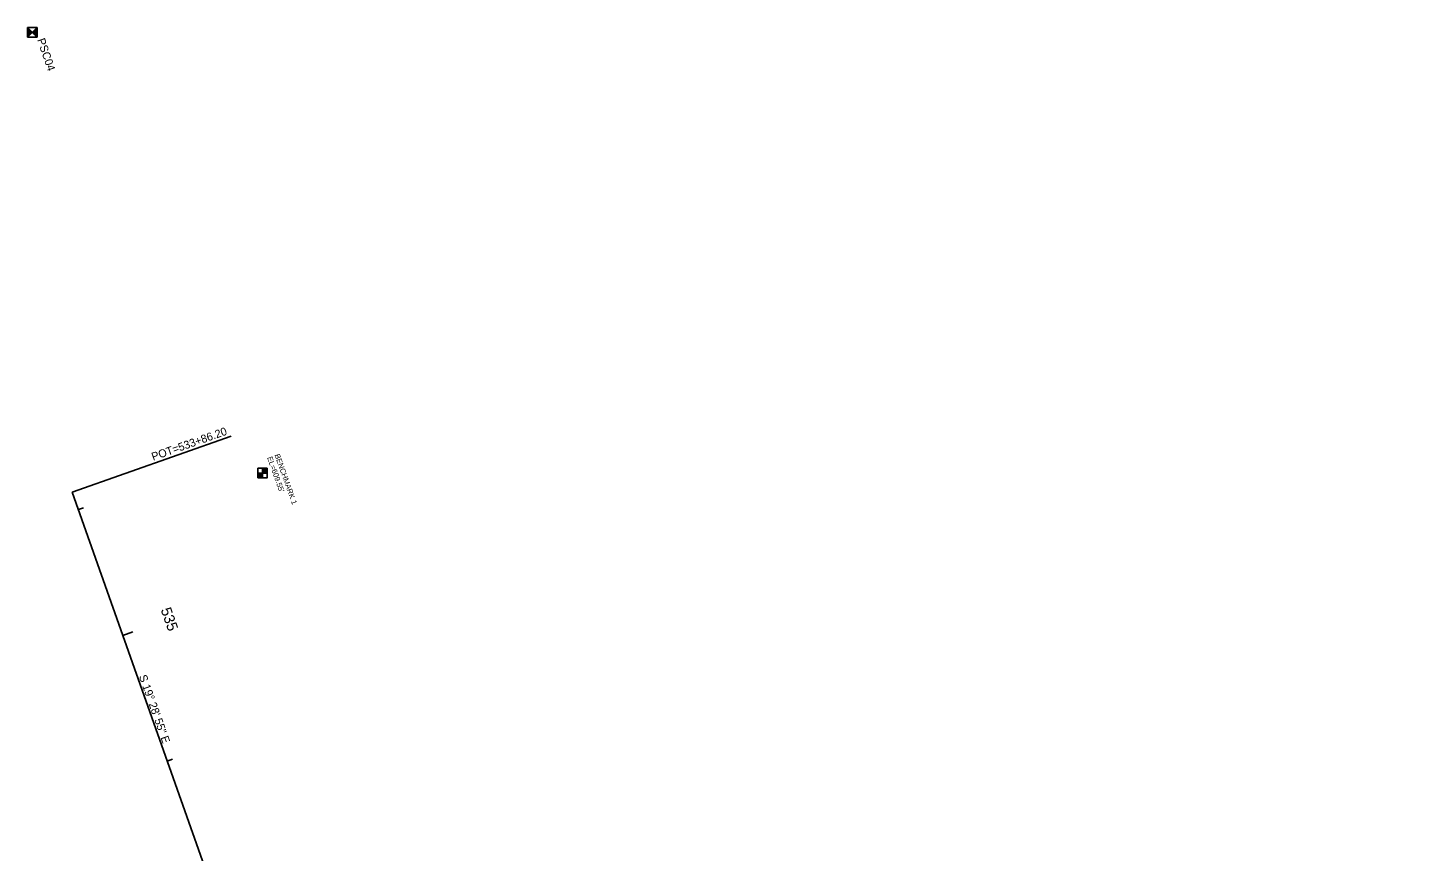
# Model space of a CAD drawing. Extents: x 2004390 to 2008791, y 1133870 to 1140084.
# Drawn here: x 2005003 to 2006039, y 1139364 to 1139982 of the extents above; entities that cross this region are included whole.
import ezdxf

# ---------------------------------------------------------------- set-up
doc = ezdxf.new("R2010")
doc.units = 0
for name, color, linetype in [('RD_HC_Cl', 7, 'Continuous'), ('RD_HC_Data', 7, 'Continuous'), ('RD_HC_Data_Tic', 7, 'Continuous'), ('RD_HC_Survey', 7, 'Continuous'), ('RD_HC_Survey_txCode', 7, 'Continuous'), ('RD_HC_TX_Sta50', 7, 'Continuous')]:
    doc.layers.add(name, color=color, linetype=linetype)

msp = doc.modelspace()

# ---------------------------------------------------------------- linework, layer by layer
at = {"layer": 'RD_HC_Cl'}
msp.add_line((2005036.1, 1139633.5), (2007075.2, 1133869.8), dxfattribs=at)
at = {"layer": 'RD_HC_Data'}
msp.add_line((2005036.1, 1139633.5), (2005155.4, 1139675.7), dxfattribs=at)
at = {"layer": 'RD_HC_Data_Tic'}
for p, q in [((2005040.7, 1139620.5), (2005044.5, 1139621.9)), ((2005074.1, 1139526.2), (2005081.6, 1139528.9)), ((2005107.4, 1139432), (2005111.2, 1139433.3))]:
    msp.add_line(p, q, dxfattribs=at)
at = {"layer": 'RD_HC_Survey'}
for p, q in [((2005002.6, 1139981.9), (2005009.7, 1139974.8)), ((2005009.7, 1139981.9), (2005002.6, 1139974.8)), ((2005002.7, 1139981.8), (2005002.7, 1139974.9)), ((2005002.7, 1139981.8), (2005002.7, 1139974.9)), ((2005002.8, 1139981.7), (2005002.8, 1139975)), ((2005002.8, 1139981.7), (2005002.8, 1139975)), ((2005002.9, 1139981.6), (2005002.9, 1139975.1)), ((2005002.9, 1139981.6), (2005002.9, 1139975.1)), ((2005003, 1139981.5), (2005003, 1139975.2)), ((2005003, 1139981.5), (2005003, 1139975.2)), ((2005003.1, 1139981.4), (2005003.1, 1139975.3)), ((2005003.1, 1139981.4), (2005003.1, 1139975.3)), ((2005003.2, 1139981.3), (2005003.2, 1139975.4)), ((2005003.2, 1139981.3), (2005003.2, 1139975.4)), ((2005003.3, 1139981.2), (2005003.3, 1139975.5)), ((2005003.3, 1139981.2), (2005003.3, 1139975.5)), ((2005003.4, 1139981.1), (2005003.4, 1139975.6)), ((2005003.4, 1139981.1), (2005003.4, 1139975.6)), ((2005003.5, 1139981), (2005003.5, 1139975.7)), ((2005003.5, 1139981), (2005003.5, 1139975.7)), ((2005003.6, 1139980.9), (2005003.6, 1139975.8)), ((2005003.6, 1139980.9), (2005003.6, 1139975.8)), ((2005003.7, 1139980.8), (2005003.7, 1139975.9)), ((2005003.7, 1139980.8), (2005003.7, 1139975.9)), ((2005003.8, 1139980.7), (2005003.8, 1139976)), ((2005003.8, 1139980.7), (2005003.8, 1139976)), ((2005003.9, 1139980.6), (2005003.9, 1139976.1)), ((2005003.9, 1139980.6), (2005003.9, 1139976.1)), ((2005004, 1139980.5), (2005004, 1139976.2)), ((2005004, 1139980.5), (2005004, 1139976.2)), ((2005004.1, 1139980.4), (2005004.1, 1139976.3)), ((2005004.1, 1139980.4), (2005004.1, 1139976.3)), ((2005004.2, 1139980.3), (2005004.2, 1139976.4)), ((2005004.2, 1139980.3), (2005004.2, 1139976.4)), ((2005004.3, 1139980.2), (2005004.3, 1139976.5)), ((2005004.3, 1139980.2), (2005004.3, 1139976.5)), ((2005004.4, 1139980.1), (2005004.4, 1139976.6)), ((2005004.4, 1139980.1), (2005004.4, 1139976.6)), ((2005004.5, 1139980), (2005004.5, 1139976.7)), ((2005004.5, 1139980), (2005004.5, 1139976.7)), ((2005004.6, 1139979.9), (2005004.6, 1139976.8)), ((2005004.6, 1139979.9), (2005004.6, 1139976.8)), ((2005004.7, 1139979.8), (2005004.7, 1139976.9)), ((2005004.7, 1139979.8), (2005004.7, 1139976.9)), ((2005004.8, 1139979.7), (2005004.8, 1139977)), ((2005004.8, 1139979.7), (2005004.8, 1139977)), ((2005004.9, 1139979.6), (2005004.9, 1139977.1)), ((2005004.9, 1139979.6), (2005004.9, 1139977.1)), ((2005005, 1139979.5), (2005005, 1139977.2)), ((2005005, 1139979.5), (2005005, 1139977.2)), ((2005005.1, 1139979.4), (2005005.1, 1139977.3)), ((2005005.1, 1139979.4), (2005005.1, 1139977.3)), ((2005005.2, 1139979.3), (2005005.2, 1139977.4)), ((2005005.2, 1139979.3), (2005005.2, 1139977.4)), ((2005005.3, 1139979.2), (2005005.3, 1139977.5)), ((2005005.3, 1139979.2), (2005005.3, 1139977.5)), ((2005005.4, 1139979.1), (2005005.4, 1139977.6)), ((2005005.4, 1139979.1), (2005005.4, 1139977.6)), ((2005005.5, 1139979), (2005005.5, 1139977.7)), ((2005005.5, 1139979), (2005005.5, 1139977.7)), ((2005005.6, 1139978.9), (2005005.6, 1139977.8)), ((2005005.6, 1139978.9), (2005005.6, 1139977.8)), ((2005005.7, 1139978.8), (2005005.7, 1139977.9)), ((2005005.7, 1139978.8), (2005005.7, 1139977.9)), ((2005005.8, 1139978.7), (2005005.8, 1139978)), ((2005005.8, 1139978.7), (2005005.8, 1139978)), ((2005005.9, 1139978.6), (2005005.9, 1139978.1)), ((2005005.9, 1139978.6), (2005005.9, 1139978.1)), ((2005006, 1139978.5), (2005006, 1139978.2)), ((2005006, 1139978.5), (2005006, 1139978.2)), ((2005006.1, 1139978.4), (2005006.1, 1139978.3)), ((2005006.1, 1139978.4), (2005006.1, 1139978.3)), ((2005006.2, 1139978.4), (2005006.2, 1139978.3)), ((2005006.3, 1139978.5), (2005006.3, 1139978.2)), ((2005006.3, 1139978.4), (2005006.3, 1139978.3)), ((2005006.4, 1139978.6), (2005006.4, 1139978.1)), ((2005006.4, 1139978.5), (2005006.4, 1139978.2)), ((2005006.5, 1139978.7), (2005006.5, 1139978)), ((2005006.5, 1139978.6), (2005006.5, 1139978.1)), ((2005006.6, 1139978.8), (2005006.6, 1139977.9)), ((2005006.6, 1139978.7), (2005006.6, 1139978)), ((2005006.7, 1139978.9), (2005006.7, 1139977.8)), ((2005006.7, 1139978.8), (2005006.7, 1139977.9)), ((2005006.8, 1139979), (2005006.8, 1139977.7)), ((2005006.8, 1139978.9), (2005006.8, 1139977.8)), ((2005006.9, 1139979.1), (2005006.9, 1139977.6)), ((2005006.9, 1139979), (2005006.9, 1139977.7)), ((2005007, 1139979.2), (2005007, 1139977.5)), ((2005007, 1139979.1), (2005007, 1139977.6)), ((2005007.1, 1139979.3), (2005007.1, 1139977.4)), ((2005007.1, 1139979.2), (2005007.1, 1139977.5)), ((2005007.2, 1139979.4), (2005007.2, 1139977.3)), ((2005007.2, 1139979.3), (2005007.2, 1139977.4)), ((2005007.3, 1139979.5), (2005007.3, 1139977.2)), ((2005007.3, 1139979.4), (2005007.3, 1139977.3)), ((2005007.4, 1139979.6), (2005007.4, 1139977.1)), ((2005007.4, 1139979.5), (2005007.4, 1139977.2)), ((2005007.5, 1139979.7), (2005007.5, 1139977)), ((2005007.5, 1139979.6), (2005007.5, 1139977.1)), ((2005007.6, 1139979.8), (2005007.6, 1139976.9)), ((2005007.6, 1139979.7), (2005007.6, 1139977)), ((2005007.7, 1139979.9), (2005007.7, 1139976.8)), ((2005007.7, 1139979.8), (2005007.7, 1139976.9)), ((2005007.8, 1139980), (2005007.8, 1139976.7)), ((2005007.8, 1139979.9), (2005007.8, 1139976.8)), ((2005007.9, 1139980.1), (2005007.9, 1139976.6)), ((2005007.9, 1139980), (2005007.9, 1139976.7)), ((2005008, 1139980.2), (2005008, 1139976.5)), ((2005008, 1139980.1), (2005008, 1139976.6)), ((2005008.1, 1139980.3), (2005008.1, 1139976.4)), ((2005008.1, 1139980.2), (2005008.1, 1139976.5)), ((2005008.2, 1139980.4), (2005008.2, 1139976.3)), ((2005008.2, 1139980.3), (2005008.2, 1139976.4)), ((2005008.3, 1139980.5), (2005008.3, 1139976.2)), ((2005008.3, 1139980.4), (2005008.3, 1139976.3)), ((2005008.4, 1139980.6), (2005008.4, 1139976.1)), ((2005008.4, 1139980.5), (2005008.4, 1139976.2)), ((2005008.5, 1139980.7), (2005008.5, 1139976)), ((2005008.5, 1139980.6), (2005008.5, 1139976.1)), ((2005008.6, 1139980.8), (2005008.6, 1139975.9)), ((2005008.6, 1139980.7), (2005008.6, 1139976)), ((2005008.7, 1139980.9), (2005008.7, 1139975.8)), ((2005008.7, 1139980.8), (2005008.7, 1139975.9)), ((2005008.8, 1139981), (2005008.8, 1139975.7)), ((2005008.8, 1139980.9), (2005008.8, 1139975.8)), ((2005008.9, 1139981.1), (2005008.9, 1139975.6)), ((2005008.9, 1139981), (2005008.9, 1139975.7)), ((2005009, 1139981.2), (2005009, 1139975.5)), ((2005009, 1139981.1), (2005009, 1139975.6)), ((2005009.1, 1139981.3), (2005009.1, 1139975.4)), ((2005009.1, 1139981.2), (2005009.1, 1139975.5)), ((2005009.2, 1139981.4), (2005009.2, 1139975.3)), ((2005009.2, 1139981.3), (2005009.2, 1139975.4)), ((2005009.3, 1139981.5), (2005009.3, 1139975.2)), ((2005009.3, 1139981.4), (2005009.3, 1139975.3)), ((2005009.4, 1139981.6), (2005009.4, 1139975.1)), ((2005009.4, 1139981.5), (2005009.4, 1139975.2)), ((2005009.5, 1139981.7), (2005009.5, 1139975)), ((2005009.5, 1139981.6), (2005009.5, 1139975.1)), ((2005009.6, 1139981.8), (2005009.6, 1139974.9)), ((2005009.6, 1139981.7), (2005009.6, 1139975)), ((2005009.7, 1139981.8), (2005009.7, 1139974.9)), ((2005178.8, 1139651.5), (2005178.8, 1139644.4)), ((2005178.9, 1139651.5), (2005178.9, 1139647.9)), ((2005178.9, 1139651.5), (2005178.9, 1139647.9)), ((2005179, 1139651.5), (2005179, 1139647.9)), ((2005179, 1139651.5), (2005179, 1139647.9)), ((2005179.1, 1139651.5), (2005179.1, 1139647.9)), ((2005179.1, 1139651.5), (2005179.1, 1139647.9)), ((2005179.2, 1139651.5), (2005179.2, 1139647.9)), ((2005179.2, 1139651.5), (2005179.2, 1139647.9)), ((2005179.3, 1139651.5), (2005179.3, 1139647.9)), ((2005179.3, 1139651.5), (2005179.3, 1139647.9)), ((2005179.4, 1139651.5), (2005179.4, 1139647.9)), ((2005179.4, 1139651.5), (2005179.4, 1139647.9)), ((2005179.5, 1139651.5), (2005179.5, 1139647.9)), ((2005179.5, 1139651.5), (2005179.5, 1139647.9)), ((2005179.6, 1139651.5), (2005179.6, 1139647.9)), ((2005179.6, 1139651.5), (2005179.6, 1139647.9)), ((2005179.7, 1139651.5), (2005179.7, 1139647.9)), ((2005179.7, 1139651.5), (2005179.7, 1139647.9)), ((2005179.8, 1139651.5), (2005179.8, 1139647.9)), ((2005179.8, 1139651.5), (2005179.8, 1139647.9)), ((2005179.9, 1139651.5), (2005179.9, 1139647.9)), ((2005179.9, 1139651.5), (2005179.9, 1139647.9)), ((2005180, 1139651.5), (2005180, 1139647.9)), ((2005180, 1139651.5), (2005180, 1139647.9)), ((2005180.1, 1139651.5), (2005180.1, 1139647.9)), ((2005180.1, 1139651.5), (2005180.1, 1139647.9)), ((2005180.2, 1139651.5), (2005180.2, 1139647.9)), ((2005180.2, 1139651.5), (2005180.2, 1139647.9)), ((2005180.3, 1139651.5), (2005180.3, 1139647.9)), ((2005180.3, 1139651.5), (2005180.3, 1139647.9)), ((2005180.4, 1139651.5), (2005180.4, 1139647.9)), ((2005180.4, 1139651.5), (2005180.4, 1139647.9)), ((2005180.5, 1139651.5), (2005180.5, 1139647.9)), ((2005180.5, 1139651.5), (2005180.5, 1139647.9)), ((2005180.6, 1139651.5), (2005180.6, 1139647.9)), ((2005180.6, 1139651.5), (2005180.6, 1139647.9)), ((2005180.7, 1139651.5), (2005180.7, 1139647.9)), ((2005180.7, 1139651.5), (2005180.7, 1139647.9)), ((2005180.8, 1139651.5), (2005180.8, 1139647.9)), ((2005180.8, 1139651.5), (2005180.8, 1139647.9)), ((2005180.9, 1139651.5), (2005180.9, 1139647.9)), ((2005180.9, 1139651.5), (2005180.9, 1139647.9)), ((2005181, 1139651.5), (2005181, 1139647.9)), ((2005181, 1139651.5), (2005181, 1139647.9)), ((2005181.1, 1139651.5), (2005181.1, 1139647.9)), ((2005181.1, 1139651.5), (2005181.1, 1139647.9)), ((2005181.2, 1139651.5), (2005181.2, 1139647.9)), ((2005181.2, 1139651.5), (2005181.2, 1139647.9)), ((2005181.3, 1139651.5), (2005181.3, 1139647.9)), ((2005181.3, 1139651.5), (2005181.3, 1139647.9)), ((2005181.4, 1139651.5), (2005181.4, 1139647.9)), ((2005181.4, 1139651.5), (2005181.4, 1139647.9)), ((2005181.5, 1139651.5), (2005181.5, 1139647.9)), ((2005181.5, 1139651.5), (2005181.5, 1139647.9)), ((2005181.6, 1139651.5), (2005181.6, 1139647.9)), ((2005181.6, 1139651.5), (2005181.6, 1139647.9)), ((2005181.7, 1139651.5), (2005181.7, 1139647.9)), ((2005181.7, 1139651.5), (2005181.7, 1139647.9)), ((2005181.8, 1139651.5), (2005181.8, 1139647.9)), ((2005181.8, 1139651.5), (2005181.8, 1139647.9)), ((2005181.9, 1139651.5), (2005181.9, 1139647.9)), ((2005181.9, 1139651.5), (2005181.9, 1139647.9)), ((2005182, 1139651.5), (2005182, 1139647.9)), ((2005182, 1139651.5), (2005182, 1139647.9)), ((2005182.1, 1139651.5), (2005182.1, 1139647.9)), ((2005182.1, 1139651.5), (2005182.1, 1139647.9)), ((2005182.2, 1139651.5), (2005182.2, 1139647.9)), ((2005182.2, 1139651.5), (2005182.2, 1139647.9)), ((2005182.3, 1139651.5), (2005182.3, 1139647.9)), ((2005182.3, 1139651.5), (2005182.3, 1139647.9)), ((2005182.4, 1139647.9), (2005175.3, 1139647.9)), ((2005175.3, 1139647.9), (2005175.3, 1139644.4)), ((2005175.4, 1139647.9), (2005175.4, 1139644.4)), ((2005175.4, 1139647.9), (2005175.4, 1139644.4)), ((2005175.5, 1139647.9), (2005175.5, 1139644.4)), ((2005175.5, 1139647.9), (2005175.5, 1139644.4)), ((2005175.6, 1139647.9), (2005175.6, 1139644.4)), ((2005175.6, 1139647.9), (2005175.6, 1139644.4)), ((2005175.7, 1139647.9), (2005175.7, 1139644.4)), ((2005175.7, 1139647.9), (2005175.7, 1139644.4)), ((2005175.8, 1139647.9), (2005175.8, 1139644.4)), ((2005175.8, 1139647.9), (2005175.8, 1139644.4)), ((2005175.9, 1139647.9), (2005175.9, 1139644.4)), ((2005175.9, 1139647.9), (2005175.9, 1139644.4)), ((2005176, 1139647.9), (2005176, 1139644.4)), ((2005176, 1139647.9), (2005176, 1139644.4)), ((2005176.1, 1139647.9), (2005176.1, 1139644.4)), ((2005176.1, 1139647.9), (2005176.1, 1139644.4)), ((2005176.2, 1139647.9), (2005176.2, 1139644.4)), ((2005176.2, 1139647.9), (2005176.2, 1139644.4)), ((2005176.3, 1139647.9), (2005176.3, 1139644.4)), ((2005176.3, 1139647.9), (2005176.3, 1139644.4)), ((2005176.4, 1139647.9), (2005176.4, 1139644.4)), ((2005176.4, 1139647.9), (2005176.4, 1139644.4)), ((2005176.5, 1139647.9), (2005176.5, 1139644.4)), ((2005176.5, 1139647.9), (2005176.5, 1139644.4)), ((2005176.6, 1139647.9), (2005176.6, 1139644.4)), ((2005176.6, 1139647.9), (2005176.6, 1139644.4)), ((2005176.7, 1139647.9), (2005176.7, 1139644.4)), ((2005176.7, 1139647.9), (2005176.7, 1139644.4)), ((2005176.8, 1139647.9), (2005176.8, 1139644.4)), ((2005176.8, 1139647.9), (2005176.8, 1139644.4)), ((2005176.9, 1139647.9), (2005176.9, 1139644.4)), ((2005176.9, 1139647.9), (2005176.9, 1139644.4)), ((2005177, 1139647.9), (2005177, 1139644.4)), ((2005177, 1139647.9), (2005177, 1139644.4)), ((2005177.1, 1139647.9), (2005177.1, 1139644.4)), ((2005177.1, 1139647.9), (2005177.1, 1139644.4)), ((2005177.2, 1139647.9), (2005177.2, 1139644.4)), ((2005177.2, 1139647.9), (2005177.2, 1139644.4)), ((2005177.3, 1139647.9), (2005177.3, 1139644.4)), ((2005177.3, 1139647.9), (2005177.3, 1139644.4)), ((2005177.4, 1139647.9), (2005177.4, 1139644.4)), ((2005177.4, 1139647.9), (2005177.4, 1139644.4)), ((2005177.5, 1139647.9), (2005177.5, 1139644.4)), ((2005177.5, 1139647.9), (2005177.5, 1139644.4)), ((2005177.6, 1139647.9), (2005177.6, 1139644.4)), ((2005177.6, 1139647.9), (2005177.6, 1139644.4)), ((2005177.7, 1139647.9), (2005177.7, 1139644.4)), ((2005177.7, 1139647.9), (2005177.7, 1139644.4)), ((2005177.8, 1139647.9), (2005177.8, 1139644.4)), ((2005177.8, 1139647.9), (2005177.8, 1139644.4)), ((2005177.9, 1139647.9), (2005177.9, 1139644.4)), ((2005177.9, 1139647.9), (2005177.9, 1139644.4)), ((2005178, 1139647.9), (2005178, 1139644.4)), ((2005178, 1139647.9), (2005178, 1139644.4)), ((2005178.1, 1139647.9), (2005178.1, 1139644.4)), ((2005178.1, 1139647.9), (2005178.1, 1139644.4)), ((2005178.2, 1139647.9), (2005178.2, 1139644.4)), ((2005178.2, 1139647.9), (2005178.2, 1139644.4)), ((2005178.3, 1139647.9), (2005178.3, 1139644.4)), ((2005178.3, 1139647.9), (2005178.3, 1139644.4)), ((2005178.4, 1139647.9), (2005178.4, 1139644.4)), ((2005178.4, 1139647.9), (2005178.4, 1139644.4)), ((2005178.5, 1139647.9), (2005178.5, 1139644.4)), ((2005178.5, 1139647.9), (2005178.5, 1139644.4)), ((2005178.6, 1139647.9), (2005178.6, 1139644.4)), ((2005178.6, 1139647.9), (2005178.6, 1139644.4)), ((2005178.7, 1139647.9), (2005178.7, 1139644.4)), ((2005178.7, 1139647.9), (2005178.7, 1139644.4)), ((2005178.8, 1139647.9), (2005178.8, 1139644.4)), ((2005178.8, 1139647.9), (2005178.8, 1139644.4))]:
    msp.add_line(p, q, dxfattribs=at)
for points in [[(2005009.7, 1139981.9), (2005002.6, 1139981.9), (2005002.6, 1139974.8), (2005009.7, 1139974.8)], [(2005182.4, 1139651.5), (2005175.3, 1139651.5), (2005175.3, 1139644.4), (2005182.4, 1139644.4)]]:
    msp.add_lwpolyline(points, close=True, dxfattribs=at)

# ---------------------------------------------------------------- texts
at = {"layer": 'RD_HC_Data'}
for s, rotation, p in [('POT=533+86.20', 19.482, (2005096.8, 1139657.1)), ('S 19%%d 28\' 55" E', 289.482, (2005086, 1139495.5))]:
    msp.add_text(s, height=6, rotation=rotation, dxfattribs=at).set_placement(p)
at = {"layer": 'RD_HC_Survey_txCode'}
for s, height, rotation, p in [('PSC04', 6, 288.8025, (2005009.7, 1139972.8)), ('BENCHMARK 1', 4, 289.4494, (2005187.8, 1139661.5)), ("EL=609.55'", 4, 289.4494, (2005182.2, 1139659.5))]:
    msp.add_text(s, height=height, rotation=rotation, dxfattribs=at).set_placement(p)
at = {"layer": 'RD_HC_TX_Sta50'}
msp.add_text('535', height=8, rotation=289.482, dxfattribs=at).set_placement((2005102.3, 1139545.5))

doc.saveas('drawing.dxf')
